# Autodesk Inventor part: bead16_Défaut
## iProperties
Shininess: 64.0
Length Units: 11269
Angle Units: 11279
Time Units: 11290
Mass Units: 11283
Length Display Precision: 3
Angle Display Precision: 2
Compacted: True
Part Number: bead16_Défaut
Document SubType Name: Modeling
Created: 2006-01
Material: Par défaut
Designer: Fricot
Density: 0.0
Volumn: 0.0
Area: 0.0
PropertySet Name: Model Information
Control State: 0
Master: False
Checked Out: False
Author: Fricot
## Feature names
1. Base1
